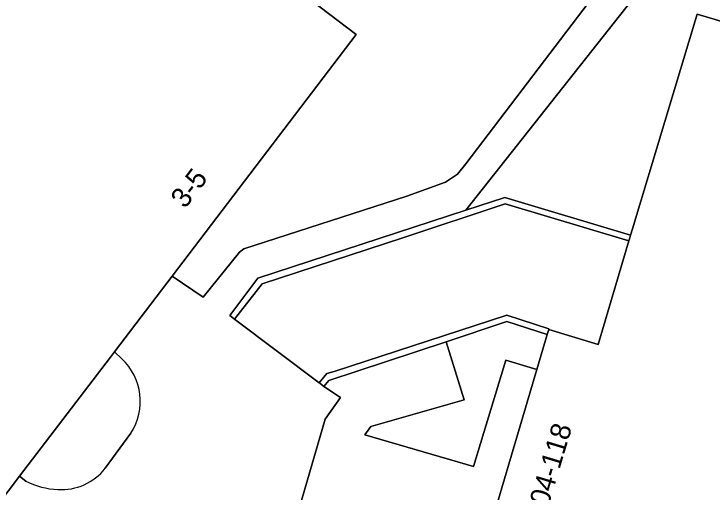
# Model space of a CAD drawing. Extents: x 161139 to 161601, y 381708 to 382245.
# Drawn here: x 161373.8 to 161408.54, y 381862.38 to 381886.2 of the extents above; entities that cross this region are included whole.
import ezdxf

# ---------------------------------------------------------------- set-up
doc = ezdxf.new("R2010")
doc.units = 0
for name, color, linetype in [('IMGEO_Groenvoorziening', 7, 'Continuous'), ('IMGEO_Hek', 7, 'Continuous'), ('IMGEO_Muur', 7, 'Continuous'), ('IMGEO_Pand', 7, 'Continuous'), ('IMGEO_Pand_nummerreeks', 7, 'Continuous'), ('IMGEO_Rijbaan_lokaal_open', 7, 'Continuous'), ('IMGEO_Voetpad_gesloten', 7, 'Continuous'), ('IMGEO_Voetpad_open', 7, 'Continuous')]:
    doc.layers.add(name, color=color, linetype=linetype)

msp = doc.modelspace()

# ---------------------------------------------------------------- linework, layer by layer
at = {"layer": 'IMGEO_Groenvoorziening'}
for points in [[(161368.776, 381898.292), (161375.084, 381893.489), (161376.851, 381895.819), (161390.838, 381885.171), (161381.677, 381873.144), (161383.219, 381872.094), (161385.019, 381874.335), (161385.244, 381874.499), (161393.345, 381877.126), (161395.275, 381877.818), (161395.877, 381878.224), (161396.293, 381878.738), (161410.212, 381897.05)], [(161425.633, 381884.432), (161423.964, 381885.944), (161411.648, 381895.891), (161396.286, 381876.416), (161398.229, 381877.051), (161404.489, 381875.181), (161404.584, 381875.499), (161407.805, 381886.188), (161423.433, 381881.545), (161420.059, 381870.284), (161418.513, 381865.051), (161414.917, 381852.938), (161413.344, 381847.686), (161410.014, 381836.444), (161394.402, 381841.083), (161397.689, 381852.301)], [(161379.167, 381869.023), (161378.802, 381869.369), (161378.602, 381869.107), (161374.079, 381863.168), (161374.394, 381862.928)], [(161378.344, 381863.568), (161379.62, 381865.312)]]:
    msp.add_lwpolyline(points, dxfattribs=at)
msp.add_lwpolyline([(161400.337, 381870.225), (161398.337, 381870.875), (161395.311, 381869.871), (161396.198, 381866.981), (161391.555, 381865.65), (161391.264, 381865.226), (161396.671, 381863.647), (161398.279, 381868.954), (161399.821, 381868.48)], close=True, dxfattribs=at)
for centre, radius, start, end in [((161377.177, 381866.897), 2.912, 327.0244, 46.8949), ((161376.187, 381865.229), 2.722, 265.8866, 322.3905), ((161376.08, 381866.145), 3.632, 242.341, 268.61)]:
    msp.add_arc(centre, radius, start, end, dxfattribs=at)
at = {"layer": 'IMGEO_Hek'}
msp.add_lwpolyline([(161378.602, 381869.107), (161381.677, 381873.144)], dxfattribs=at)
at = {"layer": 'IMGEO_Muur'}
for points in [[(161398.229, 381877.051), (161396.286, 381876.416), (161385.946, 381873.035), (161384.544, 381871.18), (161384.784, 381871), (161386.159, 381872.748), (161393.152, 381875.047), (161398.239, 381876.735), (161404.403, 381874.894), (161404.449, 381875.049), (161404.489, 381875.181)], [(161390.886, 381868.403), (161395.311, 381869.871), (161398.337, 381870.875), (161400.337, 381870.225), (161400.411, 381870.476), (161400.422, 381870.513), (161398.335, 381871.191), (161389.733, 381868.393), (161389.367, 381868.28), (161388.983, 381867.825), (161389.02, 381867.798), (161389.223, 381867.644), (161389.475, 381867.942)]]:
    msp.add_lwpolyline(points, close=True, dxfattribs=at)
at = {"layer": 'IMGEO_Pand'}
for points in [[(161390.838, 381885.171), (161376.851, 381895.819), (161375.084, 381893.489), (161373.955, 381892.001), (161370.262, 381894.819), (161369.955, 381894.435), (161364, 381886.63), (161365.51, 381885.478), (161362.5, 381881.493), (161362.266, 381881.673), (161355.333, 381872.637), (161355.437, 381872.558), (161368.964, 381862.254), (161371.759, 381860.122), (161374.079, 381863.168), (161378.602, 381869.107), (161378.802, 381869.369), (161381.677, 381873.144)], [(161418.513, 381865.051), (161411.633, 381867.094), (161413.178, 381872.321), (161413.216, 381872.31), (161420.059, 381870.284), (161423.433, 381881.545), (161407.805, 381886.188), (161404.584, 381875.499), (161404.489, 381875.181), (161404.449, 381875.049), (161404.403, 381874.894), (161402.871, 381869.734), (161400.411, 381870.476), (161400.337, 381870.225), (161399.821, 381868.48), (161396.815, 381858.319), (161399.261, 381857.59), (161397.689, 381852.301), (161394.402, 381841.083), (161410.014, 381836.444), (161413.344, 381847.686), (161406.469, 381849.737), (161408.039, 381854.979), (161414.917, 381852.938)]]:
    msp.add_lwpolyline(points, close=True, dxfattribs=at)
at = {"layer": 'IMGEO_Rijbaan_lokaal_open'}
for points in [[(161410.212, 381897.05), (161396.293, 381878.738), (161395.877, 381878.224), (161395.275, 381877.818), (161393.345, 381877.126), (161385.244, 381874.499), (161385.019, 381874.335), (161383.219, 381872.094), (161381.677, 381873.144), (161378.802, 381869.369), (161379.167, 381869.023)], [(161389.585, 381851.709), (161389.721, 381851.996), (161392.214, 381859.719), (161387.882, 381861.165), (161389.294, 381866.012), (161390.047, 381867.09), (161389.223, 381867.644), (161389.02, 381867.798), (161388.983, 381867.825), (161384.784, 381871), (161384.544, 381871.18), (161385.946, 381873.035), (161396.286, 381876.416), (161411.648, 381895.891)], [(161379.62, 381865.312), (161378.344, 381863.568)], [(161374.394, 381862.928), (161374.079, 381863.168), (161371.759, 381860.122), (161368.964, 381862.254), (161360.411, 381856.63), (161360.621, 381856.311)]]:
    msp.add_lwpolyline(points, dxfattribs=at)
for centre, radius, start, end in [((161377.177, 381866.897), 2.912, 327.0244, 46.8949), ((161376.187, 381865.229), 2.722, 265.8866, 322.3905), ((161376.08, 381866.145), 3.632, 242.341, 268.61)]:
    msp.add_arc(centre, radius, start, end, dxfattribs=at)
at = {"layer": 'IMGEO_Voetpad_gesloten'}
msp.add_lwpolyline([(161399.821, 381868.48), (161398.279, 381868.954), (161396.671, 381863.647), (161391.264, 381865.226), (161391.555, 381865.65), (161396.198, 381866.981), (161395.311, 381869.871), (161390.886, 381868.403), (161389.475, 381867.942), (161389.223, 381867.644), (161390.047, 381867.09), (161389.294, 381866.012), (161387.882, 381861.165), (161392.214, 381859.719), (161396.815, 381858.319)], close=True, dxfattribs=at)
at = {"layer": 'IMGEO_Voetpad_open'}
msp.add_lwpolyline([(161404.403, 381874.894), (161398.239, 381876.735), (161393.152, 381875.047), (161386.159, 381872.748), (161384.784, 381871), (161388.983, 381867.825), (161389.367, 381868.28), (161389.733, 381868.393), (161398.335, 381871.191), (161400.422, 381870.513), (161400.411, 381870.476), (161402.871, 381869.734)], close=True, dxfattribs=at)

# ---------------------------------------------------------------- texts
at = {"layer": 'IMGEO_Pand_nummerreeks'}
for s, rotation, p in [('3-5', 52.7007, (161382.32, 381876.464)), ('104-118', 73.3214, (161400.178, 381860.917))]:
    msp.add_text(s, height=1, rotation=rotation, dxfattribs=at).set_placement(p)

doc.saveas('drawing.dxf')
